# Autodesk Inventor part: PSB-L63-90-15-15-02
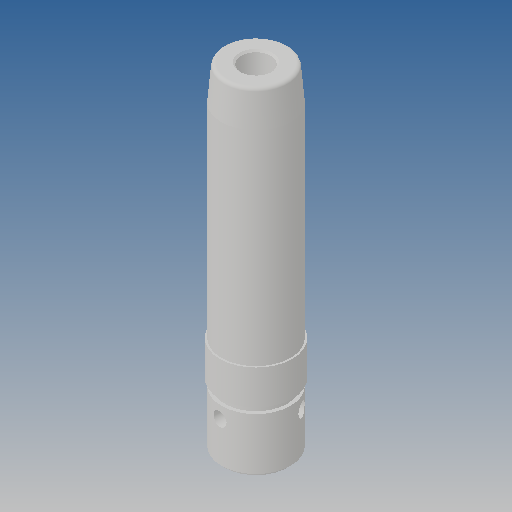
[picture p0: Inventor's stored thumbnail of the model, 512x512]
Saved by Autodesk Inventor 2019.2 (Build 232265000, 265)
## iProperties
Created: 2013-04
Part Number: PSB-L63-90-15-15-02
Material: Ogólny
Document SubType Name: Modeling
Designer: CADENGINEERING4
Density: 1 g/cm^3
Appearance: Domyślna
Author: CADENGINEERING4
Revision Number: ÈÎºÎ
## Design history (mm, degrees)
feature "µ¹½Ç1"
node "Bryła1"
